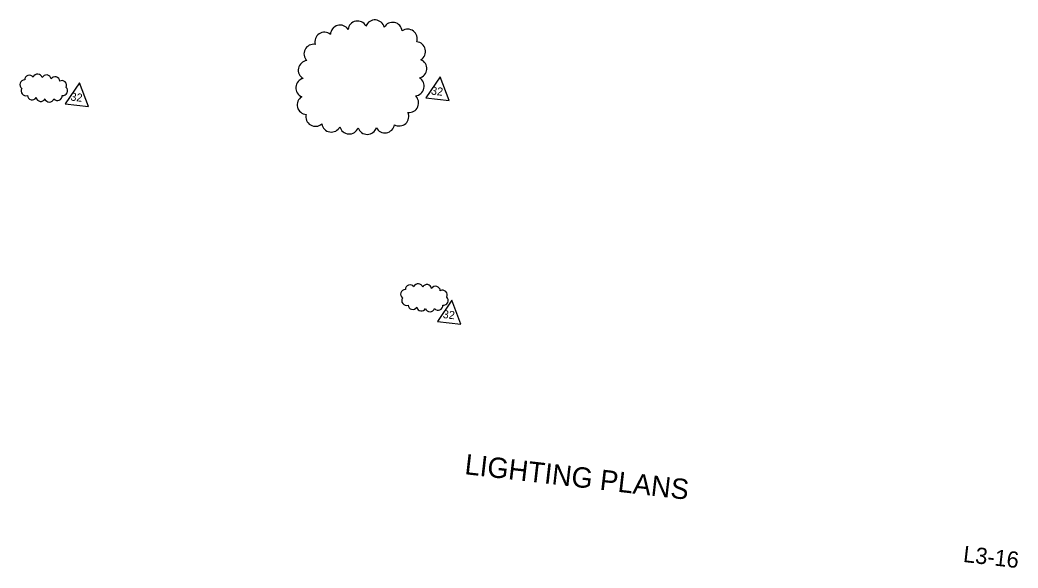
# Model space of a CAD drawing. Extents: x 926540 to 927877, y 636188 to 637075.
# Drawn here: x 927299 to 927789.8, y 636187.5 to 636457.1 of the extents above; entities that cross this region are included whole.
import ezdxf

# ---------------------------------------------------------------- set-up
doc = ezdxf.new("R2010")
doc.units = 0
for name, color, linetype in [('Cloud_dp', 7, 'Continuous'), ('TextMisc', 7, 'Continuous'), ('TextShtNo', 7, 'Continuous')]:
    doc.layers.add(name, color=color, linetype=linetype)

msp = doc.modelspace()

# ---------------------------------------------------------------- linework, layer by layer
at = {"layer": 'Cloud_dp'}
for points in [[(927505.59, 636429.18), (927498.58, 636418.78), (927510.05, 636417.46)], [(927328.3, 636426.21), (927321.29, 636415.82), (927332.76, 636414.5)], [(927511.36, 636319.22), (927504.35, 636308.83), (927515.83, 636307.51)]]:
    msp.add_lwpolyline(points, close=True, dxfattribs=at)
for centre, radius, start, end in [((927465.04, 636451.91), 4.71, 28.5202, 173.5202), ((927473.56, 636452.43), 4.71, 13.4622, 158.4622), ((927456.4, 636449.89), 4.71, 32.833, 177.833), ((927482.26, 636451.25), 4.71, 6.0578, 151.0578), ((927489.68, 636447.9), 4.71, 340.4183, 125.4183), ((927448.72, 636446.41), 4.71, 50.8928, 195.8928), ((927443.4, 636440.48), 4.71, 80.3096, 225.3096), ((927493.77, 636441.63), 4.71, 300.7949, 85.7949), ((927440.56, 636432.44), 4.71, 95.7759, 240.7759), ((927494.42, 636433.21), 4.71, 283.0639, 68.0639), ((927301.33, 636425.31), 2.31, 88.7452, 233.7452), ((927303.69, 636427.65), 2.31, 35.9239, 180.9239), ((927307.72, 636428.2), 2.31, 14.5063, 159.5063), ((927312.04, 636427.78), 2.31, 9.419, 154.419), ((927316.26, 636426.92), 2.31, 2.5433, 147.5433), ((927319.66, 636424.99), 2.31, 333.2842, 118.2842), ((927439.35, 636423.75), 4.71, 103.3705, 248.3705), ((927493.1, 636424.56), 4.71, 274.5213, 59.5213), ((927301.87, 636422.15), 2.31, 145.7808, 290.7808), ((927320.14, 636422.27), 2.31, 261.7982, 46.7982), ((927304.99, 636420.16), 2.31, 184.2521, 329.2521), ((927309.26, 636419.36), 2.31, 189.2335, 334.2335), ((927313.54, 636419.03), 2.31, 197.1278, 342.1278), ((927317.51, 636419.8), 2.31, 219.6762, 4.6762), ((927440.07, 636415.35), 4.71, 121.4345, 266.4345), ((927490.35, 636416.34), 4.71, 263.4861, 48.4861), ((927444.35, 636409.52), 4.71, 166.2268, 311.2268), ((927485.54, 636409.69), 4.71, 239.7426, 24.7426), ((927452.11, 636406.69), 4.71, 188.6752, 333.6752), ((927460.9, 636405.75), 4.71, 194.1002, 339.1002), ((927469.78, 636405.55), 4.71, 198.2978, 343.2978), ((927478.5, 636406.31), 4.71, 206.612, 351.612), ((927488.48, 636322.2), 2.31, 88.7452, 233.7452), ((927490.84, 636324.55), 2.31, 35.9239, 180.9239), ((927494.87, 636325.09), 2.31, 14.5063, 159.5063), ((927499.19, 636324.67), 2.31, 9.419, 154.419), ((927503.41, 636323.81), 2.31, 2.5433, 147.5433), ((927506.81, 636321.88), 2.31, 333.2842, 118.2842), ((927489.03, 636319.05), 2.31, 145.7808, 290.7808), ((927507.29, 636319.16), 2.31, 261.7982, 46.7982), ((927492.15, 636317.06), 2.31, 184.2521, 329.2521), ((927496.41, 636316.25), 2.31, 189.2335, 334.2335), ((927500.69, 636315.93), 2.31, 197.1278, 342.1278), ((927504.66, 636316.69), 2.31, 219.6762, 4.6762)]:
    msp.add_arc(centre, radius, start, end, dxfattribs=at)

# ---------------------------------------------------------------- texts
for p in [(927501, 636420.5), (927323.71, 636417.53), (927506.78, 636310.54)]:
    msp.add_text('32', height=3.938, rotation=353.433, dxfattribs=at).set_placement(p)
at = {"layer": 'TextMisc'}
msp.add_text('        LIGHTING PLANS         ', height=10, rotation=353.433, dxfattribs=at).set_placement((927487.84, 636237.13))
at = {"layer": 'TextShtNo'}
msp.add_text('L3-16 ', height=8, rotation=353.433, dxfattribs=at).set_placement((927762.55, 636190.55))

doc.saveas('drawing.dxf')
